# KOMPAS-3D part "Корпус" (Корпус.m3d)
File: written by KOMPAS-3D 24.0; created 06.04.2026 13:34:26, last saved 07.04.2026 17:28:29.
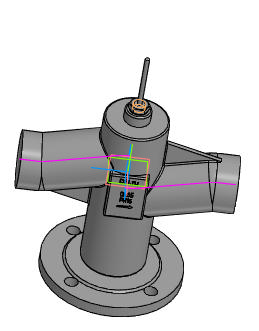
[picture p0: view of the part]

Document properties: Автор: R2D2; Полное имя файла: E:\Работа\Зайцев\Солянка\VSR1-13V-PED-F Клапан запорно-регулирующий DN.ru\DN65\исходные материалы\Корпус.m3d

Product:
- Body: Труба / Нестандартная труба / L = 143.5 мм  | qty 1
    Материал: Нестандартная труба (density 7856 kg/m3)
    Масса: 18.070121
    Раздел спецификации: Детали
    Примечание: 4,98 кг
    additional columns: Pipeline; 0.075; 0; 0; 0.002; 0.14351; true; 0.04
- Body: Труба / Нестандартная труба / L = 143.5 мм  | qty 1
    Материал: Нестандартная труба (density 7856 kg/m3)
    Масса: 18.070121
    Раздел спецификации: Детали
    Форматы листов документа: БЧ
    Примечание: 4,98 кг
    additional columns: Pipeline; 0.075; 0; 0; 0.002; 0.14351; true; 0.04
- Component [standard]: Гайка М16-6H ГОСТ 5916-70  | qty 1  | Масса: 0.01768; Рассекать на разрезах: no; source file: C:\Program Files\ASCON\KOMPAS-3D v24\Libs\PolynomLib\DATA\vault\Methods\Kompas\3D\PLib_Nut_OST92_900.m3d
- Component [standard]: (unnamed)  | qty 1  | Материал: ВЧ40 ГОСТ 7293-85 (density 7200 kg/m3); Масса: 2.948314; Рассекать на разрезах: no; additional columns: 65-16-B-2-ВЧ40-II; Заглушка; ГОСТ 34785-2021
- Body: Тело 4  | qty 1
    Материал: Нестандартная труба (density 7856 kg/m3)
    Масса: 18.070121
- Part/product: Корпус
    Масса: 6.9

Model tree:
1. Эскиз:1
2. Труба:1  (labels: {F703FF30-5BE6-4673-A7F1-8EDA1BE1E2D1}; SHAPEOBJECT3D_ATTR_BUTT; SHAPEOBJECT3D_ATTR_VALID; SHAPEOBJECT3D_ATTR_BUTT_AREA)
     PIPE_R = 7
3. Труба:2  (labels: {F703FF30-5BE6-4673-A7F1-8EDA1BE1E2D1}; SHAPEOBJECT3D_ATTR_BUTT; SHAPEOBJECT3D_ATTR_VALID; SHAPEOBJECT3D_ATTR_BUTT_AREA)
     PIPE_R = 7
4. Эскиз:2
5. Элемент выдавливания:1
     Расстояние 1 = 106; Смещение 1 = -1; Расстояние 2 = 142; Смещение 2 = -5
6. РЕБРО  (with: Ребро.Труба:1, Грань.Элемент выдавливания:1, Грань.Труба:1, Грань.Труба:2)
7. Элемент выдавливания:2
     Расстояние 1 = 6
8. Эскиз:4  (with: Грань.Элемент выдавливания:1)
9. Скругление:3  (with: Ребро.Элемент выдавливания:2)
10. Элемент выдавливания:3
     Расстояние 1 = 1
11. Эскиз:5  (with: Грань.Элемент выдавливания:3)
12. Элемент выдавливания:4
     Расстояние 1 = 7.5; Смещение 1 = 0.5
13. ШТОК
14. Элемент выдавливания:5
15. ОТЛИВКА
16. Скругление:6  (with: Грань.Элемент выдавливания:1)
17. Элемент выдавливания:6  (with: Грань.Элемент выдавливания:1)
     Смещение 1 = 4
18. Эскиз:8  (with: Грань.Элемент выдавливания:6)
19. Элемент выдавливания:7
     Расстояние 1 = 0.5
20. Скругление:7  (with: Ребро.Элемент выдавливания:6)
     Радиус = 2
21. Эскиз:9  (with: Грань.Элемент выдавливания:1, Ребро.Скругление:6, Ребро.Элемент выдавливания:5)
22. Элемент вращения:1
     Угол 1 = 360
23. Скругление:8  (with: Ребро.Элемент вращения:1)
     Радиус = 2
24. Эскиз:10  (labels: Ребро.Bolt hole.Экземпляр ( 1, 2 ); Ребро.Bolt hole.Экземпляр ( 1, 6 ); Ребро.Bolt hole.Экземпляр ( 1, 4 ); Ребро.Bolt hole.Экземпляр ( 1, 8 ))
25. Элемент выдавливания:8  (with: Грань.Элемент выдавливания:3)
     Расстояние 1 = -15; Угол = 22.5

Expressions: DS/2+3; v22*2
Referenced files in C:\Program Files\ASCON\KOMPAS-3D v24\Libs\Pipeline\: StylesTemplate.a3d, TemplateHPH, InsulationStylesTemplate.a3d, Insulation
Referenced files in C:\Program Files\ASCON\KOMPAS-3D v24\Templates\: Констр. чертеж А3 гориз. перв. лист.cdt
Referenced files in E:\Работа\Зайцев\Солянка\VSR1-13V-PED-F Клапан запорно-регулирующий DN.ru\DN15\DN15 Kv0.16\исходные материалы\: 
Referenced files in C:\Program Files\ASCON\KOMPAS-3D v24\Libs\PolynomLib\DATA\vault\Methods\Kompas\3D\: PLib_Nut_OST92_900.m3d, PLib_Flange_Blind_GOST_34785_2100.m3d
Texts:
  Отводы ГОСТ 17375-2001
  Констр. чертеж А3 гориз. перв. лист.cdt
  BOSimple***PART:2c8e7818-1586-f79e-db7d-bc045ba468e4***SHORTLOC:Root±30±10±20±©{}110±10±50±80[Нет;Без покрытия;Без указания материала;-;16;2;24]
  BOSimple***Material:38d6725a-5efe-48e1-b177-a7817acb862a
  BOSimple***PART:bf56cdc1-6b07-34c9-b21f-19055cc73af8***SHORTLOC:B619_EF039B503CC34112[2;16;65;Круглая;II;ВЧ40 ГОСТ 7293-85]
  var3D
  GOST 2.304 type A
  PN16
  LL-10
  DN+10
  bcut1
  hole1
  hcut1
  hole2
  cut1
  Труба / Нестандартная труба / L = %s мм
  Plane. Начало координат
  Ось Y.Начало координат
  Плоскость ZX.Начало координат
  Горизонтальная плоскость. Начало координат
  Плоскость XY.Начало координат
  Плоскость ZY.Начало координат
